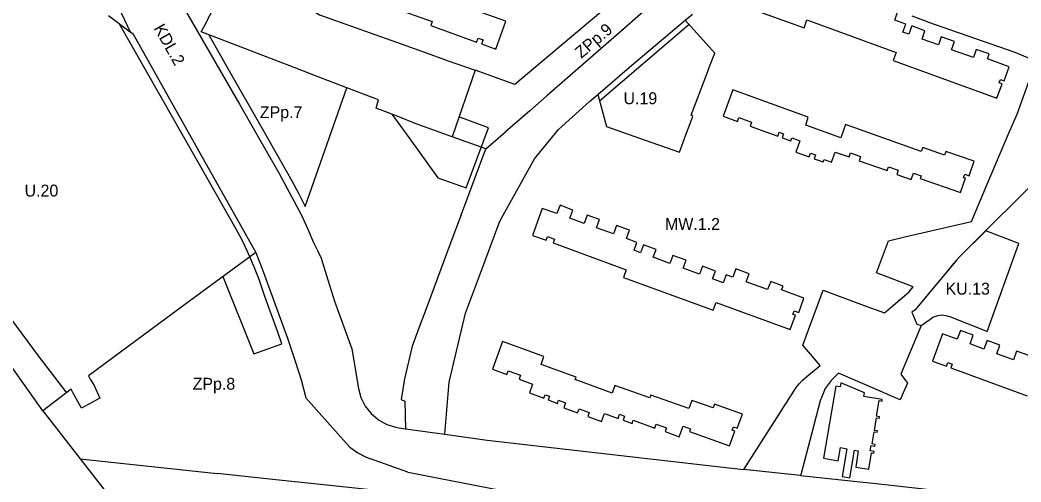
# Model space of a CAD drawing. Extents: x 7428239 to 7429836, y 5549133 to 5550853.
# Drawn here: x 7428593.3 to 7429012.7, y 5549408.8 to 5549602.4 of the extents above; entities that cross this region are included whole.
import ezdxf

# ---------------------------------------------------------------- set-up
doc = ezdxf.new("R2010")
doc.units = 0
for name, color, linetype in [('LIN_linie rozgraniczające', 7, 'Continuous'), ('LIN_nieprzekraczalna linia zabudowy', 7, 'Continuous'), ('LIN_obowiązująca linia zabudowy', 7, 'Continuous'), ('TXT_Oznaczenia Przeznaczenia', 7, 'Continuous')]:
    doc.layers.add(name, color=color, linetype=linetype)

msp = doc.modelspace()

# ---------------------------------------------------------------- linework, layer by layer
at = {"layer": 'LIN_linie rozgraniczające'}
for p, q in [((7428879.09, 5549627.52), (7428845.3, 5549597.93)), ((7428630.37, 5549604.36), (7428639.46, 5549597.54)), ((7428872.04, 5549602.37), (7428875.05, 5549604.94)), ((7428973.59, 5549601.7), (7428967.1, 5549604.02)), ((7428832.35, 5549602.13), (7428800.57, 5549575.41)), ((7428848.74, 5549582.6), (7428872.04, 5549602.37)), ((7428973.59, 5549601.7), (7429010.07, 5549588.99)), ((7428845.3, 5549597.93), (7428814.08, 5549570.59)), ((7429010.07, 5549588.99), (7429018.99, 5549585.19)), ((7428783.95, 5549581.36), (7428774.34, 5549553.53)), ((7428800.57, 5549575.41), (7428783.95, 5549581.36)), ((7428835.35, 5549571.24), (7428848.74, 5549582.6)), ((7428814.08, 5549570.59), (7428806.97, 5549564.43)), ((7428831.87, 5549568.25), (7428835.35, 5549571.24)), ((7428818.89, 5549556.54), (7428831.87, 5549568.25)), ((7428788.44, 5549548.41), (7428774.34, 5549553.53)), ((7428785.8, 5549495.17), (7428794.41, 5549518.19)), ((7428779.97, 5549479.57), (7428785.8, 5549495.17)), ((7428754.59, 5549442.73), (7428754.8, 5549431.16)), ((7428754.8, 5549431.16), (7428771.33, 5549428.84)), ((7428728.79, 5549426.29), (7428731.56, 5549423.47)), ((7428731.56, 5549423.47), (7428734.79, 5549421.04)), ((7428734.79, 5549421.04), (7428738.34, 5549419.2)), ((7428738.34, 5549419.2), (7428740.23, 5549418.55))]:
    msp.add_line(p, q, dxfattribs=at)
for points in [[(7428625.6, 5549669.31), (7428638.64, 5549650.99), (7428642.6, 5549643.34), (7428646.55, 5549635.7), (7428652.62, 5549623.4), (7428659.85, 5549611.37), (7428677, 5549581.35), (7428685.33, 5549567.22), (7428693.63, 5549552.48), (7428701.86, 5549538.11), (7428711.42, 5549520.42), (7428713.85, 5549514.82), (7428716.28, 5549509.22), (7428717.9, 5549505.9), (7428719.52, 5549502.58), (7428722.28, 5549493.59), (7428725.04, 5549484.59), (7428732.3, 5549464.59), (7428735.09, 5549448.03)], [(7428608.8, 5549665.15), (7428611.26, 5549656.29), (7428616.25, 5549638.3), (7428624.11, 5549623.93), (7428632.32, 5549611.66), (7428633.4, 5549610.24), (7428639.46, 5549597.54), (7428640.52, 5549596.75), (7428666.31, 5549550.91), (7428692.12, 5549505.06), (7428695.14, 5549497), (7428701.75, 5549479.01), (7428705.34, 5549469.11), (7428706.25, 5549466.52), (7428708.67, 5549459.09), (7428711.09, 5549451.66), (7428713.12, 5549444.13), (7428728.79, 5549426.29)], [(7428884.25, 5549645.75), (7428883.19, 5549644.86), (7428880.57, 5549642.66), (7428832.35, 5549602.13)], [(7428669.26, 5549597.47), (7428670.44, 5549599.77), (7428684.4, 5549626.97)], [(7428684.4, 5549626.97), (7428695.73, 5549619.62), (7428707.06, 5549612.28), (7428718.8, 5549604.66), (7428727.46, 5549601.57), (7428739.98, 5549597.08), (7428750.99, 5549593.15), (7428762.35, 5549589.11), (7428772.73, 5549585.38), (7428783.95, 5549581.36)], [(7428835.35, 5549571.24), (7428839.1, 5549557.76), (7428855.29, 5549552.06), (7428869.58, 5549547.03), (7428872.72, 5549555.42), (7428875.2, 5549562.06), (7428874.5, 5549562.53), (7428881.37, 5549580.63), (7428882.54, 5549583.71), (7428884.36, 5549588.53), (7428872.04, 5549602.37)], [(7428774.34, 5549553.53), (7428758.84, 5549559.12), (7428752.06, 5549561.79), (7428749.08, 5549562.97), (7428742.57, 5549565.54), (7428743.5, 5549568.93), (7428741.29, 5549569.78), (7428730.28, 5549574.01), (7428717.82, 5549578.8), (7428708.13, 5549582.53), (7428695.05, 5549587.55), (7428682.41, 5549592.41), (7428669.26, 5549597.47)], [(7429024.28, 5549540.35), (7428987.13, 5549503.3), (7428985.66, 5549501.81), (7428968.31, 5549480.96), (7428966.93, 5549479.93), (7428969.02, 5549474.97), (7428970.91, 5549474.46), (7428970.28, 5549472.96), (7428962.35, 5549454.04), (7428965.19, 5549450.27), (7428963.38, 5549446.16), (7428962.07, 5549443.26), (7428962.06, 5549443.26), (7428958.14, 5549444.93), (7428952.45, 5549447.4), (7428936.23, 5549454.43), (7428933.14, 5549451.32), (7428930.63, 5549447.95), (7428928.51, 5549442.88), (7428924.18, 5549426.2), (7428920.58, 5549412.32), (7428920.34, 5549411.54), (7428912.2, 5549412.42), (7428900.54, 5549413.67), (7428896.51, 5549414.1), (7428910.42, 5549435.69), (7428918.52, 5549448.43), (7428919.83, 5549450.02), (7428920.98, 5549451.42), (7428923.77, 5549453.69), (7428928.6, 5549457.66), (7428921.28, 5549466.14), (7428929.8, 5549489.19), (7428946.99, 5549482.81), (7428955.53, 5549479.72), (7428965.87, 5549488.47), (7428967.58, 5549490.57), (7428952.2, 5549496.48), (7428957.23, 5549509.84), (7428964.65, 5549511.71), (7428992.02, 5549518.01), (7428998.56, 5549533.58), (7429007.84, 5549555.7), (7429011.13, 5549563.04), (7429018.99, 5549585.19)], [(7428692.12, 5549505.06), (7428664.86, 5549484.98), (7428621.96, 5549453.36), (7428622.78, 5549451.92), (7428624.33, 5549449.21), (7428626.78, 5549444.02), (7428619.09, 5549439.74), (7428615.65, 5549446.03), (7428614.73, 5549447.7), (7428602.83, 5549438.62), (7428514.4, 5549563.66)], [(7428806.97, 5549564.43), (7428796.69, 5549555.54)], [(7428778.1, 5549520.75), (7428778.66, 5549522.24), (7428788.44, 5549548.41), (7428796.69, 5549555.54)], [(7428794.41, 5549518.19), (7428808.84, 5549544.25), (7428818.89, 5549556.54)], [(7428778.1, 5549520.75), (7428773.82, 5549509.3), (7428762.64, 5549479.2), (7428761.44, 5549475.93), (7428757.67, 5549465.79), (7428754.34, 5549452.03), (7428753.03, 5549443.33), (7428754.59, 5549442.73)], [(7428970.91, 5549474.46), (7428974.5, 5549476.93), (7428975.81, 5549477.85), (7428977.87, 5549478.66), (7428979.49, 5549478.82), (7428981.17, 5549478.63), (7428983.23, 5549478.05), (7428989.85, 5549475.39), (7428997.28, 5549472.43), (7428998.57, 5549471.91), (7429011.82, 5549508.71), (7428997.94, 5549514.08)], [(7428771.33, 5549428.84), (7428773.06, 5549450.63), (7428779.97, 5549479.57)], [(7428735.09, 5549448.03), (7428736.15, 5549444.18), (7428737.95, 5549440.61), (7428740.42, 5549437.47), (7428743.46, 5549434.89), (7428746.96, 5549432.96), (7428750.78, 5549431.77), (7428752.03, 5549431.55), (7428754.8, 5549431.16)], [(7428602.83, 5549438.62), (7428618.49, 5549418.54), (7428675.97, 5549412.33)], [(7428771.33, 5549428.84), (7428789.02, 5549426.35), (7428896.48, 5549414.1)], [(7428618.49, 5549418.54), (7428651.96, 5549375.64)], [(7428755.81, 5549412.91), (7428740.23, 5549418.55)], [(7428826.76, 5549396.33), (7428816.76, 5549397.43), (7428815.8, 5549397.49), (7428778.99, 5549401.37), (7428757.12, 5549403.69), (7428724.48, 5549407.19), (7428703.17, 5549409.39), (7428675.97, 5549412.33)], [(7428755.81, 5549412.91), (7428758.02, 5549412.48), (7428800.35, 5549404.28), (7428814.55, 5549402.65)], [(7428920.34, 5549411.54), (7428951.94, 5549408.14), (7428957.12, 5549407.58), (7429009.09, 5549401.82), (7429027.13, 5549395.01), (7429041.39, 5549393.62), (7429059.28, 5549391.87), (7429065.83, 5549391.23), (7429085.85, 5549389.28), (7429090.38, 5549392.28), (7429092.31, 5549393.56), (7429092.68, 5549393.81)]]:
    msp.add_lwpolyline(points, dxfattribs=at)
at = {"layer": 'LIN_nieprzekraczalna linia zabudowy'}
for p, q in [((7428873.68, 5549600.52), (7428836.14, 5549568.39)), ((7428712.77, 5549524.24), (7428730.28, 5549574.01)), ((7428789.61, 5549557.27), (7428777.23, 5549561.9))]:
    msp.add_line(p, q, dxfattribs=at)
for points in [[(7428689.65, 5549503.24), (7428688.53, 5549505.7), (7428686.3, 5549510.41), (7428683.87, 5549514.76), (7428672.12, 5549535.42), (7428657.18, 5549561.75), (7428634.92, 5549600.94)], [(7428672.44, 5549596.25), (7428680.43, 5549582.15), (7428695.34, 5549555.95), (7428707.21, 5549535.01), (7428710.11, 5549529.6), (7428712.77, 5549524.24)], [(7428749.08, 5549562.97), (7428751.33, 5549559.87), (7428756.62, 5549552.57), (7428768.41, 5549536.36), (7428780.2, 5549532.08)], [(7428538.48, 5549556.89), (7428533.38, 5549552.9), (7428535.68, 5549549.86), (7428600.98, 5549461.67), (7428612.81, 5549446.24)], [(7428780.2, 5549532.08), (7428789.61, 5549557.27)], [(7428997.94, 5549514.08), (7428987.13, 5549503.3), (7428984.47, 5549500.38), (7428980.91, 5549496.11), (7428976.43, 5549490.72), (7428968.31, 5549480.96), (7428966.93, 5549479.93)], [(7428703, 5549466.75), (7428701.27, 5549471.62), (7428695.95, 5549486.61), (7428693.45, 5549493.69), (7428691.62, 5549498.59), (7428689.65, 5549503.24)], [(7428678.32, 5549494.89), (7428691.28, 5549462.59), (7428703, 5549466.75)]]:
    msp.add_lwpolyline(points, dxfattribs=at)
at = {"layer": 'LIN_obowiązująca linia zabudowy'}
for points in [[(7428739.82, 5549611.23), (7428766.02, 5549601.84), (7428765.38, 5549600.07), (7428784.59, 5549593.13), (7428785.22, 5549594.88), (7428787.3, 5549594.13), (7428786.67, 5549592.38), (7428792.73, 5549590.19), (7428796.91, 5549601.89), (7428769.94, 5549611.65)], [(7428894.23, 5549609.12), (7428921.79, 5549599.21), (7428923, 5549602.44), (7428960.41, 5549588.86), (7428959.2, 5549585.49), (7429002.64, 5549569.73), (7429004.8, 5549575.63), (7429003.53, 5549576.09), (7429004.05, 5549577.51), (7429005.62, 5549576.93), (7429007.8, 5549582.86), (7428998.7, 5549586.17), (7428999.4, 5549588.2), (7428993.96, 5549590.08), (7428992.81, 5549586.76), (7428983.63, 5549589.93), (7428984.86, 5549593.49), (7428979.24, 5549595.43), (7428978.08, 5549592.05), (7428971.25, 5549594.41), (7428972.47, 5549597.93), (7428966.91, 5549599.93), (7428965.66, 5549596.45), (7428963.21, 5549597.33), (7428964.42, 5549600.71), (7428959.79, 5549602.37), (7428960.99, 5549605.7)], [(7429016.38, 5549461.7), (7429010.86, 5549463.71), (7429009.53, 5549460.05), (7429002.54, 5549462.6), (7429003.86, 5549466.22), (7428998.49, 5549468.18), (7428997.17, 5549464.56), (7428991.4, 5549466.67), (7428992.73, 5549470.31), (7428987.31, 5549472.29), (7428985.98, 5549468.64), (7428979.78, 5549470.91), (7428975.62, 5549459.45), (7428981.48, 5549457.31), (7428982.04, 5549458.84), (7428983.92, 5549458.15), (7428983.36, 5549456.62), (7429015.26, 5549444.94)]]:
    msp.add_lwpolyline(points, dxfattribs=at)
for points in [[(7428891.91, 5549573.16), (7428887.91, 5549562.11), (7428893.9, 5549559.9), (7428894.49, 5549561.55), (7428899.86, 5549559.62), (7428899.25, 5549557.93), (7428910.79, 5549553.78), (7428911.37, 5549555.45), (7428913.22, 5549554.78), (7428912.6, 5549553.07), (7428916.24, 5549551.75), (7428916.69, 5549552.99), (7428920.07, 5549551.77), (7428918.38, 5549547.08), (7428923.95, 5549545.07), (7428924.52, 5549546.68), (7428926.57, 5549545.95), (7428925.99, 5549544.3), (7428929.8, 5549542.95), (7428930.17, 5549544), (7428933.37, 5549542.87), (7428934.86, 5549547.1), (7428940.66, 5549545.05), (7428941.25, 5549546.75), (7428945.49, 5549545.27), (7428944.87, 5549543.46), (7428956.63, 5549539.37), (7428957.17, 5549540.92), (7428961.28, 5549539.49), (7428960.67, 5549537.74), (7428966.74, 5549535.63), (7428967.66, 5549538.28), (7428970.83, 5549537.18), (7428970.43, 5549536.03), (7428987.32, 5549530.15), (7428989.39, 5549536.1), (7428988.66, 5549536.35), (7428989.16, 5549537.81), (7428990.97, 5549537.18), (7428993.07, 5549543.23), (7428981.25, 5549547.34), (7428980.69, 5549545.76), (7428971.53, 5549549), (7428970.94, 5549547.35), (7428939.13, 5549558.61), (7428937.17, 5549553.09), (7428922.52, 5549558.31), (7428923.59, 5549561.67)], [(7428808.07, 5549512.17), (7428813.7, 5549510.1), (7428814.3, 5549511.75), (7428817.32, 5549510.64), (7428816.72, 5549509), (7428847.29, 5549497.79), (7428846.16, 5549494.54), (7428883.77, 5549480.88), (7428884.97, 5549484.07), (7428916.06, 5549472.77), (7428918.17, 5549478.72), (7428917.16, 5549479.07), (7428917.67, 5549480.56), (7428919.64, 5549479.86), (7428921.69, 5549485.86), (7428912.39, 5549489.33), (7428913, 5549490.96), (7428907.83, 5549492.88), (7428906.55, 5549489.44), (7428897.59, 5549492.66), (7428898.83, 5549496.1), (7428893.23, 5549498.12), (7428891.99, 5549494.67), (7428889.19, 5549495.68), (7428887.95, 5549492.32), (7428883.52, 5549493.93), (7428884.73, 5549497.24), (7428879.27, 5549499.23), (7428878.07, 5549495.92), (7428871.17, 5549498.43), (7428872.38, 5549501.82), (7428866.8, 5549503.81), (7428865.6, 5549500.46), (7428858.66, 5549502.99), (7428859.84, 5549506.32), (7428854.5, 5549508.21), (7428853.34, 5549504.93), (7428850.61, 5549505.92), (7428851.78, 5549509.26), (7428847.39, 5549510.84), (7428848.65, 5549514.35), (7428843.28, 5549516.28), (7428842.02, 5549512.77), (7428834.86, 5549515.34), (7428836.12, 5549518.79), (7428830.91, 5549520.7), (7428829.64, 5549517.22), (7428823.72, 5549519.34), (7428824.96, 5549522.81), (7428819.58, 5549524.78), (7428818.26, 5549521.31), (7428812.14, 5549523.5)], [(7428795.48, 5549467.71), (7428791.22, 5549456.12), (7428797.26, 5549453.9), (7428797.83, 5549455.46), (7428803.04, 5549453.54), (7428802.44, 5549451.9), (7428808.05, 5549449.84), (7428806.71, 5549446.18), (7428812.78, 5549443.96), (7428813.31, 5549445.4), (7428815.13, 5549444.74), (7428814.56, 5549443.21), (7428818.49, 5549441.77), (7428818.97, 5549443.05), (7428821.85, 5549442), (7428821.15, 5549439.94), (7428826.94, 5549437.81), (7428827.54, 5549439.46), (7428831.76, 5549437.93), (7428831.16, 5549436.33), (7428836.97, 5549434.17), (7428838.22, 5549437.54), (7428843.9, 5549435.43), (7428844.55, 5549437.2), (7428846.6, 5549436.45), (7428845.98, 5549434.76), (7428849.74, 5549433.39), (7428850.21, 5549434.67), (7428859.23, 5549431.38), (7428859.85, 5549433.09), (7428864.15, 5549431.52), (7428863.57, 5549429.94), (7428869.54, 5549427.76), (7428871.16, 5549432.2), (7428874.19, 5549431.09), (7428873.81, 5549430.05), (7428890.55, 5549423.94), (7428892.87, 5549430.07), (7428891.66, 5549430.53), (7428892.19, 5549431.93), (7428893.75, 5549431.34), (7428895.98, 5549437.22), (7428884.29, 5549441.4), (7428883.76, 5549439.89), (7428874.77, 5549443.02), (7428873.59, 5549439.64), (7428857.58, 5549445.2), (7428857.2, 5549444.11), (7428842.57, 5549449.27), (7428841.48, 5549446.04), (7428825.91, 5549451.76), (7428826.27, 5549452.8), (7428811.72, 5549458.09), (7428812.8, 5549461.41)], [(7428930.02, 5549418.76), (7428936.17, 5549417.73), (7428937.07, 5549423.24), (7428939.69, 5549422.79), (7428937.78, 5549411.07), (7428940.96, 5549410.53), (7428942.93, 5549422.12), (7428944.52, 5549421.82), (7428943.45, 5549415.06), (7428948.91, 5549414.16), (7428950.1, 5549421.1), (7428951.05, 5549420.95), (7428951.15, 5549421.59), (7428949.52, 5549421.85), (7428949.89, 5549424.17), (7428951.52, 5549423.91), (7428951.62, 5549424.55), (7428950.39, 5549424.75), (7428951.19, 5549429.84), (7428952.43, 5549429.64), (7428952.52, 5549430.23), (7428951.29, 5549430.43), (7428952.13, 5549435.76), (7428953.37, 5549435.57), (7428953.46, 5549436.16), (7428952.23, 5549436.35), (7428953.27, 5549442.92), (7428954.5, 5549442.73), (7428954.58, 5549443.34), (7428946.86, 5549444.64), (7428947.1, 5549446.21), (7428937.15, 5549450.36), (7428936.91, 5549448.69), (7428935.13, 5549449.03)]]:
    msp.add_lwpolyline(points, close=True, dxfattribs=at)

# ---------------------------------------------------------------- texts
at = {"layer": 'TXT_Oznaczenia Przeznaczenia'}
for s, rotation, p in [('KDL.2', 299.4552, (7428649.19, 5549599.02)), ('ZPp.9', 40.6888, (7428828.49, 5549586.08))]:
    msp.add_text(s, height=5, rotation=rotation, dxfattribs=at).set_placement(p)
for s, p in [('U.19', (7428846.17, 5549567.14)), ('ZPp.7', (7428693.8, 5549561.3)), ('U.20', (7428595.24, 5549528.45)), ('MW.1.2', (7428863.55, 5549514.46)), ('KU.13', (7428981.09, 5549487.34)), ('ZPp.8', (7428665.64, 5549447.48))]:
    msp.add_text(s, height=5, dxfattribs=at).set_placement(p)

doc.saveas('drawing.dxf')
